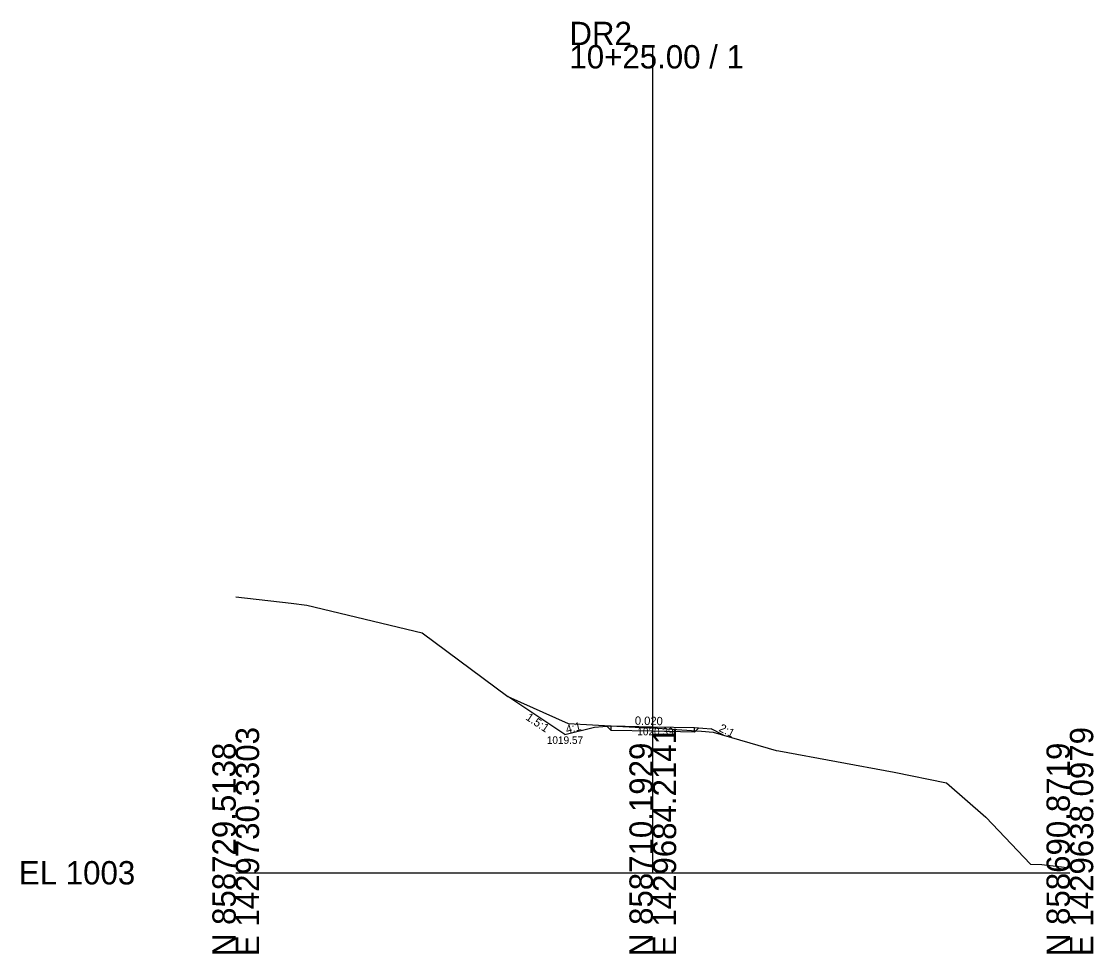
# Model space of a CAD drawing. Extents: x -26 to 103, y -10 to 3026.
# Drawn here: x -25.7 to 102.8, y 490.3 to 602.1 of the extents above; entities that cross this region are included whole.
import ezdxf

# ---------------------------------------------------------------- set-up
doc = ezdxf.new("R2010")
doc.units = 0
for name, color, linetype in [('Default', 7, 'Continuous'), ('Exist Cross Section Cell', 7, 'Continuous'), ('Exist XS Center Line Elevation Label', 7, 'Continuous'), ('Exist XS Ground Line', 7, 'Continuous'), ('Prop CMT Pvmt Surface', 7, 'Continuous'), ('Prop CMT Shld Paved Course 1', 7, 'Continuous'), ('Prop CMT Slope Grass', 7, 'Continuous'), ('Prop CMT Subgrade Earthwork', 7, 'Continuous'), ('Prop CMT Template Flag', 7, 'Continuous'), ('Prop XS SE Text', 7, 'Continuous'), ('Prop XS Side Slope Text', 7, 'Continuous')]:
    doc.layers.add(name, color=color, linetype=linetype)

msp = doc.modelspace()

# ---------------------------------------------------------------- linework, layer by layer
at = {"layer": 'Exist Cross Section Cell'}
for p, q in [((50, 500), (50, 599.28)), ((0, 500), (50, 500)), ((50, 500), (100, 500))]:
    msp.add_line(p, q, dxfattribs=at)
at = {"layer": 'Exist XS Ground Line'}
msp.add_lwpolyline([(0, 533.09), (6.65, 532.32), (8.54, 532.09), (22.33, 528.77), (32.62, 521.13), (39.84, 517.89), (48.59, 517.44), (49.92, 517.4), (55.85, 516.98), (57.25, 516.87), (64.77, 514.67), (65.12, 514.62), (78.94, 512.08), (85.19, 510.8), (89.92, 506.65), (95.26, 501.05), (96.65, 500.98), (100, 500.6)], dxfattribs=at)
at = {"layer": 'Prop CMT Pvmt Surface'}
for p, q in [((45, 517.61), (50, 517.51)), ((50, 517.51), (55, 517.41))]:
    msp.add_line(p, q, dxfattribs=at)
at = {"layer": 'Prop CMT Shld Paved Course 1'}
for points in [[(45, 517.07), (45, 517.61)], [(55, 516.87), (55, 517.41)]]:
    msp.add_lwpolyline(points, dxfattribs=at)
at = {"layer": 'Prop CMT Slope Grass'}
for p, q in [((39.47, 516.57), (32.62, 521.13)), ((39.47, 516.57), (43, 517.45)), ((43, 517.45), (45, 517.61)), ((55, 517.41), (57, 517.25)), ((58.47, 516.51), (57, 517.25))]:
    msp.add_line(p, q, dxfattribs=at)
at = {"layer": 'Prop CMT Subgrade Earthwork'}
for points in [[(45, 517.07), (44.5, 517.57)], [(55, 516.87), (55.5, 517.37)]]:
    msp.add_lwpolyline(points, dxfattribs=at)
at = {"layer": 'Prop CMT Template Flag'}
for p, q in [((50, 516.97), (45, 517.07)), ((55, 516.87), (50, 516.97))]:
    msp.add_line(p, q, dxfattribs=at)

# ---------------------------------------------------------------- texts
at = {"layer": 'Default'}
msp.add_text('1019.57', height=0.9, dxfattribs=at).set_placement((37.29, 515.46))
at = {"layer": 'Exist Cross Section Cell'}
for s, p in [('DR2', (40, 599.28)), ('10+25.00 / 1', (40, 596.48)), ('EL 1003', (-26, 498.6))]:
    msp.add_text(s, height=2.8, dxfattribs=at).set_placement(p)
for s, p in [('E 1429730.3303', (2.8, 490)), ('E 1429684.2141', (52.8, 490)), ('E 1429638.0979', (102.8, 490)), ('N 858729.5138', (0, 490)), ('N 858710.1929', (50, 490)), ('N 858690.8719', (100, 490))]:
    msp.add_text(s, height=2.8, rotation=90, dxfattribs=at).set_placement(p)
at = {"layer": 'Exist XS Center Line Elevation Label'}
msp.add_text('1020.39', height=0.9, dxfattribs=at).set_placement((48.14, 516.49))
at = {"layer": 'Prop XS SE Text'}
msp.add_text('0.020', height=1, rotation=358.8542, dxfattribs=at).set_placement((47.84, 517.76))
at = {"layer": 'Prop XS Side Slope Text'}
for s, rotation, p in [('1.5:1', 326.3099, (34.68, 518.43)), ('4:1', 14.0362, (39.69, 516.69)), ('2:1', 333.4349, (57.84, 517.03))]:
    msp.add_text(s, height=1, rotation=rotation, dxfattribs=at).set_placement(p)

doc.saveas('drawing.dxf')
